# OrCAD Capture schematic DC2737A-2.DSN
size Custom; title: 42VIN COMPACT ISOLATED FLYBACK CONVERTER; rev: 2; note: DC2737A
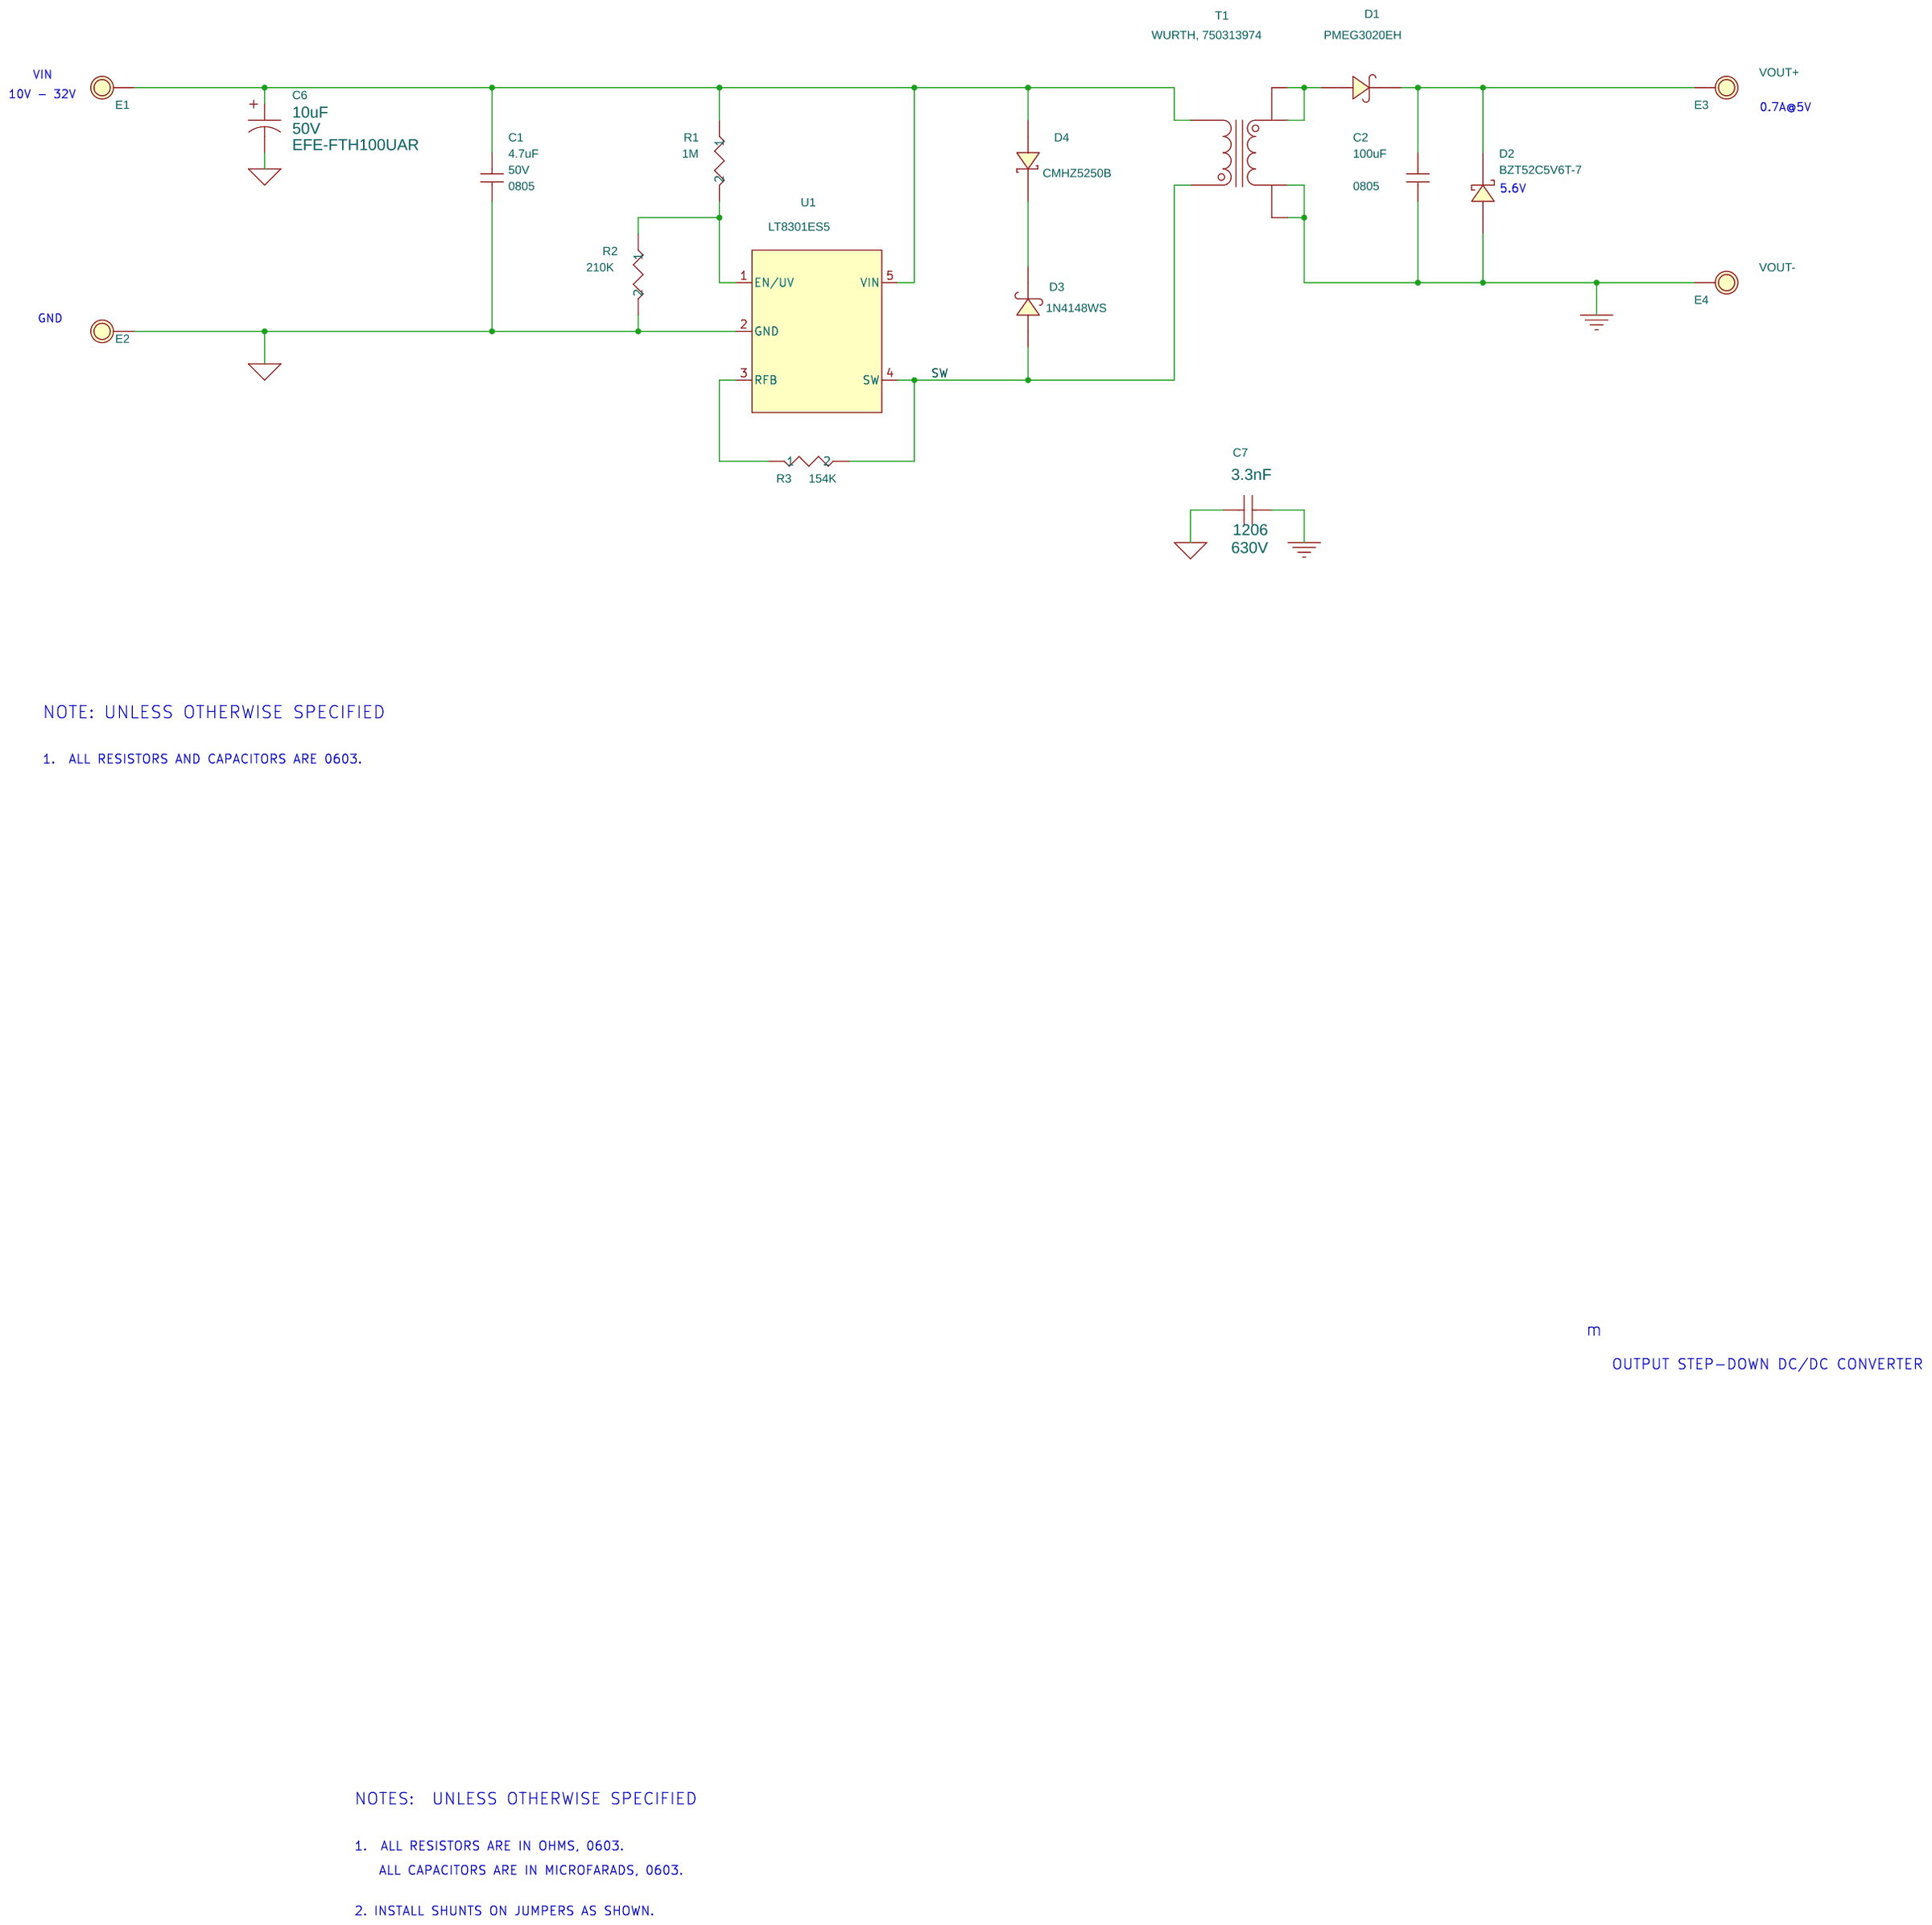
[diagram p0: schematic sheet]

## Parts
C1  4.7uF  [0805]
C2  100uF  [0805]
C6  10uF  [CAP-PANASONIC-4X5.8]
C7  3.3nF  [1206]
D1  PMEG3020EH  [POWERDI123]
D2  BZT52C5V6T-7  [SOD-523]
D3  1N4148WS  [SOD-323]
D4  CMHZ5250B  [SOD-123]
E1  E_1  [PAD150-095]
E2  E_1  [PAD150-095]
E3  VOUT+  [PAD150-095]
E4  VOUT-  [PAD150-095]
R1  1M  [0603]
R2  210K  [0603]
R3  154K  [0603]
T1  WURTH, 750313974  [TRANS-WE-750370047]
U1  LT8301ES5  [TSOT23-5]

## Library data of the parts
C1 = CAP-NP: CAP, 1210 4.7uF 10% 50V X7R; Part Number: MURATA GRM32ER71H475K; voltage: 50V
C2 = CAP-NP: CAP, 100uF 10% 6.3V X5R; Part Number: MURATA GRM32ER71A476K; voltage: 6.3V
C6 = CAP_2: CAP.,ALUM, 10uF,50V,20%; COMPGROUP: PANASONIC; COMPKEY: EFE-FTH100UAR; VOLTAGE: 50V
C7 = CAP_NP_0: 1ST PART FIELD: 630V; VOLTAGE: NPO
D1 D3 = DIODE_SCHOTTKY_3: DIODE, SCHOTTKY, BARRIER RECTIFIER 8A; Part Number: MICRO SEMI UPS840
D2 = DIODE_SCHOTTKY_4: DIODE, SCHOTTKY, BARRIER RECTIFIER 8A; Part Number: MICRO SEMI UPS840
D4 = DIODE_SCHOTTKY_5: DIODE, SCHOTTKY, BARRIER RECTIFIER 8A; Part Number: MICRO SEMI UPS840
E1-E4 = E_1: TURRET; Part Number: MILL-MAX 2501-2-00-80-00-00-07-0
R1 = R_2: RES, 0603 357K OHMS 1% 1/16W; Part Number: VISHAY CRCW0603357KFKED; Tol: 1%
R2 = R: RES, 0603 93.1K OHMS 1% 1/16W; Part Number: VISHAY CRCW060393K1FKED; Tol: 1%
R3 = R_1: RES, 0603 84.5K OHMS 1% 1/16W; Part Number: VISHAY CRCW060384K5FKED; Tol: 1%
T1 = TRANS-750370047_1
U1 = LT8300: IC, MONOLITHIC FLYBACK CONVERTER; Part Number: LINEAR TECH LT3575EFE

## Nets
DGND: C2.1 C7.1 D2.2 E4.1(A) T1.7 T1.8
GNDSIGNAL: C1.1 C6.2 C7.2 E2.1(A) R2.2 U1.2(GND)
SW: D3.2 R3.2 T1.1 U1.4(SW)
N18174949: C1.2 C6.1 D4.2 E1.1(A) R1.1 T1.4 U1.5(VIN)
N18175089: C2.2 D1.1 D2.1 E3.1(A)
N18175113: R3.1 U1.3(RFB)
N18253108: R1.2 R2.1 U1.1(EN/UV)
N18259639: D3.1 D4.1
N18271404: D1.2 T1.5 T1.6

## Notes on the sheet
- VIN
- 10V - 32V
- 0.7A@5V
- 5.6V
- GND
- NOTE: UNLESS OTHERWISE SPECIFIED
- 1.  ALL RESISTORS AND CAPACITORS ARE 0603.
- m
- OUTPUT STEP-DOWN DC/DC CONVERTER
- NOTES:  UNLESS OTHERWISE SPECIFIED
- 1.  ALL RESISTORS ARE IN OHMS, 0603.
- ALL CAPACITORS ARE IN MICROFARADS, 0603.
- 2. INSTALL SHUNTS ON JUMPERS AS SHOWN.
